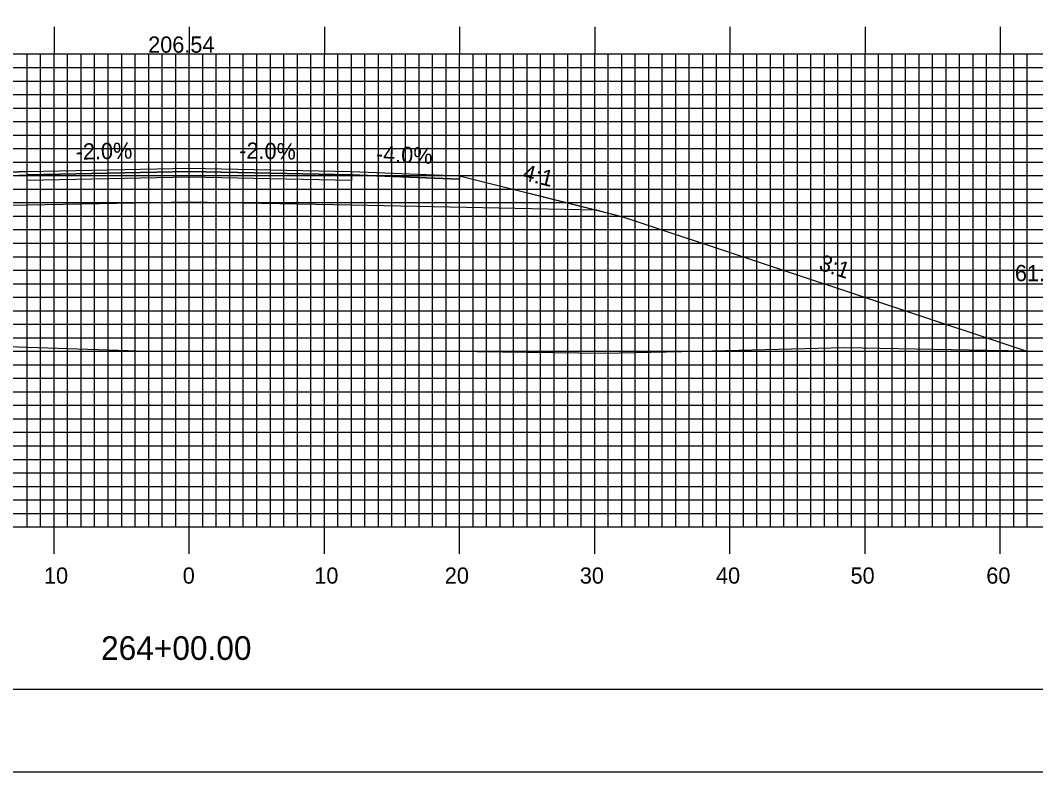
# Model space of a CAD drawing. Extents: x 1807045 to 1807388, y 442591 to 442811.
# Drawn here: x 1807198.3 to 1807273.4, y 442590.5 to 442646.2 of the extents above; entities that cross this region are included whole.
import ezdxf

# ---------------------------------------------------------------- set-up
doc = ezdxf.new("R2010")
doc.units = 0
for name, color, linetype in [('ANNOTATION', 7, 'Continuous'), ('BORDER', 7, 'Continuous'), ('D_Roadway_Centerline', 7, 'Continuous'), ('D_Roadway_Centerline_Text', 7, 'Continuous'), ('D_Roadway_Edge_Shoulder', 7, 'Continuous'), ('D_Roadway_Edge_TW', 7, 'Continuous'), ('D_Roadway_Pavement', 7, 'Continuous'), ('D_Roadway_SlopeLines', 7, 'Continuous'), ('D_Roadway_SubGrade', 7, 'Continuous'), ('D_Text_Standard', 7, 'Continuous'), ('H_V ANNOTATION', 7, 'Continuous'), ('MAJOR', 7, 'Continuous'), ('MINOR', 7, 'Continuous'), ('PLOT BOUNDARY', 7, 'Continuous'), ('S_Roadway_Centerline', 7, 'Continuous')]:
    doc.layers.add(name, color=color, linetype=linetype)

msp = doc.modelspace()

# ---------------------------------------------------------------- linework, layer by layer
at = {"layer": 'BORDER'}
msp.add_lwpolyline([(1807061.159, 442596.665), (1807381.159, 442596.665), (1807381.159, 442806.665), (1807061.159, 442806.665)], close=True, dxfattribs=at)
at = {"layer": 'D_Roadway_Centerline'}
msp.add_lwpolyline([(1807152.17, 442622.783), (1807178.759, 442631.646), (1807180.585, 442632.103), (1807190.759, 442634.646), (1807198.759, 442634.966), (1807210.759, 442635.206), (1807222.759, 442634.966), (1807230.759, 442634.646), (1807240.933, 442632.103), (1807242.759, 442631.646), (1807272.573, 442621.708)], dxfattribs=at)
at = {"layer": 'D_Roadway_Edge_Shoulder'}
for points in [[(1807198.759, 442634.966), (1807190.759, 442634.646), (1807190.759, 442634.396), (1807198.759, 442634.716)], [(1807222.759, 442634.966), (1807230.759, 442634.646), (1807230.759, 442634.396), (1807222.759, 442634.716)]]:
    msp.add_lwpolyline(points, close=True, dxfattribs=at)
at = {"layer": 'D_Roadway_Edge_TW'}
msp.add_lwpolyline([(1807198.759, 442634.716), (1807198.759, 442634.966), (1807210.759, 442635.206), (1807222.759, 442634.966), (1807222.759, 442634.716), (1807210.759, 442634.956)], close=True, dxfattribs=at)
at = {"layer": 'D_Roadway_Pavement'}
msp.add_lwpolyline([(1807198.759, 442634.3), (1807198.759, 442634.716), (1807210.759, 442634.956), (1807222.759, 442634.716), (1807222.759, 442634.3), (1807210.759, 442634.54)], close=True, dxfattribs=at)
at = {"layer": 'D_Roadway_SlopeLines'}
msp.add_lwpolyline([(1807230.759, 442634.646), (1807242.759, 442631.646), (1807272.573, 442621.708)], dxfattribs=at)
at = {"layer": 'D_Roadway_SubGrade'}
msp.add_lwpolyline([(1807198.759, 442632.466), (1807180.585, 442632.103), (1807190.759, 442634.646), (1807190.759, 442634.396), (1807198.759, 442634.716), (1807210.759, 442634.956), (1807222.759, 442634.716), (1807230.759, 442634.396), (1807230.759, 442634.646), (1807240.933, 442632.103), (1807222.759, 442632.466), (1807210.759, 442632.706)], close=True, dxfattribs=at)
at = {"layer": 'MAJOR'}
for p, q in [((1807200.759, 442645.669), (1807200.759, 442643.665)), ((1807210.759, 442645.669), (1807210.759, 442643.665)), ((1807220.759, 442645.669), (1807220.759, 442643.665)), ((1807230.759, 442645.669), (1807230.759, 442643.665)), ((1807240.759, 442645.669), (1807240.759, 442643.665)), ((1807250.759, 442645.669), (1807250.759, 442643.665)), ((1807260.759, 442645.669), (1807260.759, 442643.665)), ((1807270.759, 442645.669), (1807270.759, 442643.665)), ((1807070.759, 442643.665), (1807350.759, 442643.665)), ((1807070.759, 442643.665), (1807350.759, 442643.665)), ((1807200.759, 442608.665), (1807200.759, 442643.665)), ((1807210.759, 442608.665), (1807210.759, 442643.665)), ((1807220.759, 442608.665), (1807220.759, 442643.665)), ((1807230.759, 442608.665), (1807230.759, 442643.665)), ((1807240.759, 442608.665), (1807240.759, 442643.665)), ((1807250.759, 442608.665), (1807250.759, 442643.665)), ((1807260.759, 442608.665), (1807260.759, 442643.665)), ((1807270.759, 442608.665), (1807270.759, 442643.665)), ((1807070.759, 442638.665), (1807350.759, 442638.665)), ((1807070.759, 442633.665), (1807350.759, 442633.665)), ((1807070.759, 442628.665), (1807350.759, 442628.665)), ((1807070.759, 442623.665), (1807350.759, 442623.665)), ((1807070.759, 442618.665), (1807350.759, 442618.665)), ((1807070.759, 442613.665), (1807350.759, 442613.665)), ((1807070.759, 442608.665), (1807350.759, 442608.665)), ((1807070.759, 442608.665), (1807350.759, 442608.665)), ((1807200.759, 442606.661), (1807200.759, 442608.665)), ((1807210.759, 442606.661), (1807210.759, 442608.665)), ((1807220.759, 442606.661), (1807220.759, 442608.665)), ((1807230.759, 442606.661), (1807230.759, 442608.665)), ((1807240.759, 442606.661), (1807240.759, 442608.665)), ((1807250.759, 442606.661), (1807250.759, 442608.665)), ((1807260.759, 442606.661), (1807260.759, 442608.665)), ((1807270.759, 442606.661), (1807270.759, 442608.665))]:
    msp.add_line(p, q, dxfattribs=at)
at = {"layer": 'MINOR'}
for p, q in [((1807198.759, 442608.665), (1807198.759, 442643.665)), ((1807199.759, 442608.665), (1807199.759, 442643.665)), ((1807201.759, 442608.665), (1807201.759, 442643.665)), ((1807202.759, 442608.665), (1807202.759, 442643.665)), ((1807203.759, 442608.665), (1807203.759, 442643.665)), ((1807204.759, 442608.665), (1807204.759, 442643.665)), ((1807205.759, 442608.665), (1807205.759, 442643.665)), ((1807206.759, 442608.665), (1807206.759, 442643.665)), ((1807207.759, 442608.665), (1807207.759, 442643.665)), ((1807208.759, 442608.665), (1807208.759, 442643.665)), ((1807209.759, 442608.665), (1807209.759, 442643.665)), ((1807211.759, 442608.665), (1807211.759, 442643.665)), ((1807212.759, 442608.665), (1807212.759, 442643.665)), ((1807213.759, 442608.665), (1807213.759, 442643.665)), ((1807214.759, 442608.665), (1807214.759, 442643.665)), ((1807215.759, 442608.665), (1807215.759, 442643.665)), ((1807216.759, 442608.665), (1807216.759, 442643.665)), ((1807217.759, 442608.665), (1807217.759, 442643.665)), ((1807218.759, 442608.665), (1807218.759, 442643.665)), ((1807219.759, 442608.665), (1807219.759, 442643.665)), ((1807221.759, 442608.665), (1807221.759, 442643.665)), ((1807222.759, 442608.665), (1807222.759, 442643.665)), ((1807223.759, 442608.665), (1807223.759, 442643.665)), ((1807224.759, 442608.665), (1807224.759, 442643.665)), ((1807225.759, 442608.665), (1807225.759, 442643.665)), ((1807226.759, 442608.665), (1807226.759, 442643.665)), ((1807227.759, 442608.665), (1807227.759, 442643.665)), ((1807228.759, 442608.665), (1807228.759, 442643.665)), ((1807229.759, 442608.665), (1807229.759, 442643.665)), ((1807231.759, 442608.665), (1807231.759, 442643.665)), ((1807232.759, 442608.665), (1807232.759, 442643.665)), ((1807233.759, 442608.665), (1807233.759, 442643.665)), ((1807234.759, 442608.665), (1807234.759, 442643.665)), ((1807235.759, 442608.665), (1807235.759, 442643.665)), ((1807236.759, 442608.665), (1807236.759, 442643.665)), ((1807237.759, 442608.665), (1807237.759, 442643.665)), ((1807238.759, 442608.665), (1807238.759, 442643.665)), ((1807239.759, 442608.665), (1807239.759, 442643.665)), ((1807241.759, 442608.665), (1807241.759, 442643.665)), ((1807242.759, 442608.665), (1807242.759, 442643.665)), ((1807243.759, 442608.665), (1807243.759, 442643.665)), ((1807244.759, 442608.665), (1807244.759, 442643.665)), ((1807245.759, 442608.665), (1807245.759, 442643.665)), ((1807246.759, 442608.665), (1807246.759, 442643.665)), ((1807247.759, 442608.665), (1807247.759, 442643.665)), ((1807248.759, 442608.665), (1807248.759, 442643.665)), ((1807249.759, 442608.665), (1807249.759, 442643.665)), ((1807251.759, 442608.665), (1807251.759, 442643.665)), ((1807252.759, 442608.665), (1807252.759, 442643.665)), ((1807253.759, 442608.665), (1807253.759, 442643.665)), ((1807254.759, 442608.665), (1807254.759, 442643.665)), ((1807255.759, 442608.665), (1807255.759, 442643.665)), ((1807256.759, 442608.665), (1807256.759, 442643.665)), ((1807257.759, 442608.665), (1807257.759, 442643.665)), ((1807258.759, 442608.665), (1807258.759, 442643.665)), ((1807259.759, 442608.665), (1807259.759, 442643.665)), ((1807261.759, 442608.665), (1807261.759, 442643.665)), ((1807262.759, 442608.665), (1807262.759, 442643.665)), ((1807263.759, 442608.665), (1807263.759, 442643.665)), ((1807264.759, 442608.665), (1807264.759, 442643.665)), ((1807265.759, 442608.665), (1807265.759, 442643.665)), ((1807266.759, 442608.665), (1807266.759, 442643.665)), ((1807267.759, 442608.665), (1807267.759, 442643.665)), ((1807268.759, 442608.665), (1807268.759, 442643.665)), ((1807269.759, 442608.665), (1807269.759, 442643.665)), ((1807271.759, 442608.665), (1807271.759, 442643.665)), ((1807272.759, 442608.665), (1807272.759, 442643.665)), ((1807070.759, 442642.665), (1807350.759, 442642.665)), ((1807070.759, 442641.665), (1807350.759, 442641.665)), ((1807070.759, 442640.665), (1807350.759, 442640.665)), ((1807070.759, 442639.665), (1807350.759, 442639.665)), ((1807070.759, 442637.665), (1807350.759, 442637.665)), ((1807070.759, 442636.665), (1807350.759, 442636.665)), ((1807070.759, 442635.665), (1807350.759, 442635.665)), ((1807070.759, 442634.665), (1807350.759, 442634.665)), ((1807070.759, 442632.665), (1807350.759, 442632.665)), ((1807070.759, 442631.665), (1807350.759, 442631.665)), ((1807070.759, 442630.665), (1807350.759, 442630.665)), ((1807070.759, 442629.665), (1807350.759, 442629.665)), ((1807070.759, 442627.665), (1807350.759, 442627.665)), ((1807070.759, 442626.665), (1807350.759, 442626.665)), ((1807070.759, 442625.665), (1807350.759, 442625.665)), ((1807070.759, 442624.665), (1807350.759, 442624.665)), ((1807070.759, 442622.665), (1807350.759, 442622.665)), ((1807070.759, 442621.665), (1807350.759, 442621.665)), ((1807070.759, 442620.665), (1807350.759, 442620.665)), ((1807070.759, 442619.665), (1807350.759, 442619.665)), ((1807070.759, 442617.665), (1807350.759, 442617.665)), ((1807070.759, 442616.665), (1807350.759, 442616.665)), ((1807070.759, 442615.665), (1807350.759, 442615.665)), ((1807070.759, 442614.665), (1807350.759, 442614.665)), ((1807070.759, 442612.665), (1807350.759, 442612.665)), ((1807070.759, 442611.665), (1807350.759, 442611.665)), ((1807070.759, 442610.665), (1807350.759, 442610.665)), ((1807070.759, 442609.665), (1807350.759, 442609.665))]:
    msp.add_line(p, q, dxfattribs=at)
at = {"layer": 'PLOT BOUNDARY'}
msp.add_lwpolyline([(1807044.972, 442590.547), (1807384.972, 442590.547), (1807384.972, 442810.547), (1807044.972, 442810.547)], close=True, dxfattribs=at)
at = {"layer": 'S_Roadway_Centerline'}
msp.add_lwpolyline([(1807070.759, 442624.588), (1807076.532, 442624.486), (1807090.473, 442624.051), (1807101.359, 442623.602), (1807101.616, 442623.6), (1807102.663, 442623.583), (1807121.922, 442623.53), (1807124.249, 442623.473), (1807143.984, 442622.932), (1807148.174, 442622.845), (1807153.239, 442622.767), (1807171.802, 442622.883), (1807179.132, 442622.578), (1807184.653, 442622.424), (1807206.24, 442621.713), (1807206.839, 442621.699), (1807232.064, 442621.65), (1807241.46, 442621.516), (1807249.476, 442621.7), (1807259.21, 442621.932), (1807269.785, 442621.757), (1807281.757, 442621.548)], dxfattribs=at)

# ---------------------------------------------------------------- texts
at = {"layer": 'ANNOTATION'}
for s, rotation, p in [('-2.0%', 1.14576, (1807202.365, 442635.839)), ('-2.0%', 358.85424, (1807214.445, 442635.933)), ('-4.0%', 357.70939, (1807224.55, 442635.696)), ('4:1', 345.96376, (1807235.352, 442634.36)), ('3:1', 341.56522, (1807257.27, 442627.718))]:
    msp.add_text(s, height=1.2, rotation=rotation, dxfattribs=at).set_placement(p)
at = {"layer": 'D_Roadway_Centerline'}
for s, p in [('C', (1807210.754, 442635.206)), ('L', (1807210.759, 442635.199))]:
    msp.add_text(s, height=0.0146, dxfattribs=at).set_placement(p)
at = {"layer": 'D_Roadway_Centerline_Text'}
msp.add_text('206.54', height=1.2, dxfattribs=at).set_placement((1807207.719, 442643.761))
at = {"layer": 'D_Text_Standard'}
msp.add_text("61.8'", height=1.2, dxfattribs=at).set_placement((1807271.853, 442626.851))
at = {"layer": 'H_V ANNOTATION'}
for s, height, p in [('10', 1.2, (1807200.009, 442604.465)), ('0', 1.2, (1807210.277, 442604.465)), ('10', 1.2, (1807220.009, 442604.465)), ('20', 1.2, (1807229.667, 442604.465)), ('30', 1.2, (1807239.656, 442604.465)), ('40', 1.2, (1807249.731, 442604.465)), ('50', 1.2, (1807259.688, 442604.465)), ('60', 1.2, (1807269.731, 442604.465)), ('264+00.00', 1.75, (1807204.235, 442598.821))]:
    msp.add_text(s, height=height, dxfattribs=at).set_placement(p)

doc.saveas('drawing.dxf')
